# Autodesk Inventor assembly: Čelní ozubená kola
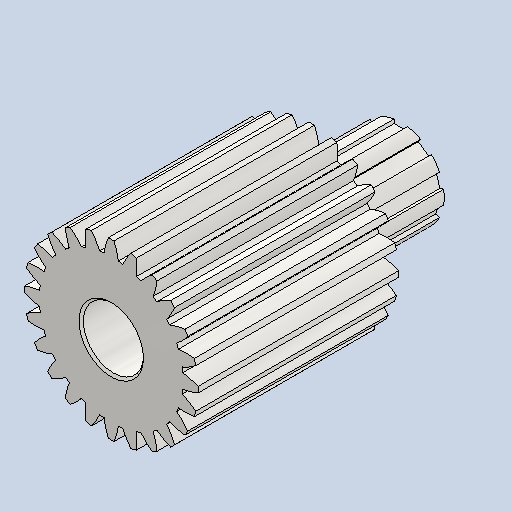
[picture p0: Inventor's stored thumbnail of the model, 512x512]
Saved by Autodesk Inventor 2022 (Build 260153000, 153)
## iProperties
ClientObjectVersion: 1
Created: 2025-05
Part Number: Čelní ozubená kola
Document SubType Name: Assembly
Designer: jbart
Categories: <?xml version="1.0" encoding="UTF-16"?> <MemberInstance><Categories><FamilyTemplate/><ParamToTemplateMap><ParamToTemplate><ParamToTemplate CategoryParameter="//
Author: jbart
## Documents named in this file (2)
- C:\Users\jbart\OneDrive\Dokumenty\Inventor\Převodovka navijáku\Hřídel III\Design Accelerator\Čelní ozubená kola1.iam
- C:\Users\jbart\OneDrive\Dokumenty\Inventor\Převodovka navijáku\Hřídel III\Design Accelerator\Čelní ozubené kolo11.ipt
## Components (1 placed, 1 different names)
1. Čelní ozubené kolo1:1
